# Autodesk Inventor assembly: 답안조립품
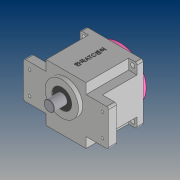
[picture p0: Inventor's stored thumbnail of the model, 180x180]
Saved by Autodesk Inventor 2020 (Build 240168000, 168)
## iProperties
Created: 2020-07
Part Number: 답안조립품
Document SubType Name: Assembly
Designer: PC312-
Author: PC312-
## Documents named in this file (10)
- C:\Users\PC312-\Desktop\700718V1002 (4)\답안조립품.iam
- C:\Users\PC312-\Desktop\700718V1002 (4)\본체.ipt
- C:\Users\PC312-\Desktop\700718V1002 (4)\커버.ipt
- C:\Users\PC312-\Desktop\700718V1002 (4)\메인 축.ipt
- C:\Users\PC312-\Desktop\700718V1002 (4)\베어링 608.ipt
- C:\Users\PC312-\Desktop\700718V1002 (4)\서브 축.ipt
- C:\Users\PC312-\Desktop\700718V1002 (4)\베어링 6003.ipt
- C:\Users\PC312-\Desktop\700718V1002 (4)\오일 실 17 32 8.ipt
- C:\Users\PC312-\Desktop\700718V1002 (4)\오일 실 8 22 7.ipt
- C:\Users\PC312-\Desktop\700718V1002 (4)\볼트 M4.ipt
